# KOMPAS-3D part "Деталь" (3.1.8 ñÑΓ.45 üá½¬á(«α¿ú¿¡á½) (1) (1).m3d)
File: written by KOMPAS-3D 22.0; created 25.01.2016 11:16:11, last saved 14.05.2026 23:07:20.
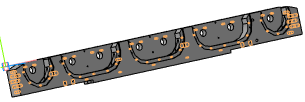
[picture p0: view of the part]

Document properties: Полное имя файла: E:\test_kompas\all_v20\3.1.8 дет.45 Балка(оригинал) (1) (1).m3d

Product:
- Part/product: Деталь
    Масса: 261.985445

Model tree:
1. Эскиз:1
2. Операция выдавливания:1
     Расстояние 1 = 115
3. Эскиз:9  (with: Операция выдавливания:1)
4. Вырезать элемент выдавливания:13
     Расстояние 1 = 115
5. Эскиз:19  (with: Операция выдавливания:1)
6. Вырезать элемент выдавливания:14
     Расстояние 1 = 231
7. Эскиз:20  (with: Операция выдавливания:1)
8. Эскиз:21  (with: Операция выдавливания:1)
9. Вырезать элемент выдавливания:15
     Расстояние 1 = 75
10. Вырезать элемент выдавливания:16
     Расстояние 1 = 10
11. Эскиз:22  (with: Операция выдавливания:1, Вырезать элемент выдавливания:14)
12. Вырезать элемент выдавливания:17
     Расстояние 1 = 30
13. Эскиз:23  (with: Операция выдавливания:1)
14. Вырезать элемент выдавливания:18
     Расстояние 1 = 30
15. Условное изображение резьбы:1  (with: Вырезать элемент выдавливания:17)
     Длина резьбы = 30; Шаг резьбы = 2; Номинальный диаметр резьбы = 20.0651
16. Условное изображение резьбы:2  (with: Вырезать элемент выдавливания:17)
     Длина резьбы = 30; Шаг резьбы = 2; Номинальный диаметр резьбы = 20.0651
17. Условное изображение резьбы:3  (with: Вырезать элемент выдавливания:18)
     Длина резьбы = 30; Шаг резьбы = 2; Номинальный диаметр резьбы = 20.0651
18. Условное изображение резьбы:4  (with: Вырезать элемент выдавливания:18)
     Длина резьбы = 30; Шаг резьбы = 2; Номинальный диаметр резьбы = 20.0651
19. Эскиз:24  (with: Операция выдавливания:1)
20. Вырезать элемент выдавливания:19
     Расстояние 1 = 75
21. Эскиз:25  (with: Операция выдавливания:1)
22. Вырезать элемент выдавливания:20
     Расстояние 1 = 35
23. Условное изображение резьбы:5  (with: Вырезать элемент выдавливания:20)
     Длина резьбы = 35; Шаг резьбы = 1.5; Номинальный диаметр резьбы = 20.0538
24. Условное изображение резьбы:6  (with: Вырезать элемент выдавливания:20)
     Длина резьбы = 35; Шаг резьбы = 1.5; Номинальный диаметр резьбы = 20.0538
25. Условное изображение резьбы:7  (with: Вырезать элемент выдавливания:20)
     Длина резьбы = 35; Шаг резьбы = 1.5; Номинальный диаметр резьбы = 20.0538
26. Условное изображение резьбы:8  (with: Вырезать элемент выдавливания:20)
     Длина резьбы = 35; Шаг резьбы = 1.5; Номинальный диаметр резьбы = 20.0538
27. Условное изображение резьбы:9  (with: Вырезать элемент выдавливания:20)
     Длина резьбы = 35; Шаг резьбы = 1; Номинальный диаметр резьбы = 19.5125
28. Условное изображение резьбы:10  (with: Вырезать элемент выдавливания:20)
     Длина резьбы = 35; Шаг резьбы = 1; Номинальный диаметр резьбы = 19.5125
29. Эскиз:26  (with: Операция выдавливания:1, Вырезать элемент выдавливания:13)
30. Вырезать элемент выдавливания:21
     Расстояние 1 = 35
31. Условное изображение резьбы:11  (with: Вырезать элемент выдавливания:21)
     Длина резьбы = 35; Шаг резьбы = 1.5; Номинальный диаметр резьбы = 20.0538
32. Условное изображение резьбы:12  (with: Вырезать элемент выдавливания:21)
     Длина резьбы = 35; Шаг резьбы = 1.5; Номинальный диаметр резьбы = 20.0538
33. Условное изображение резьбы:13  (with: Вырезать элемент выдавливания:21)
     Длина резьбы = 35; Шаг резьбы = 1.5; Номинальный диаметр резьбы = 20.0538
34. Условное изображение резьбы:14  (with: Вырезать элемент выдавливания:21)
     Длина резьбы = 35; Шаг резьбы = 1.5; Номинальный диаметр резьбы = 20.0538
35. Условное изображение резьбы:15  (with: Вырезать элемент выдавливания:21)
     Длина резьбы = 35; Шаг резьбы = 1.5; Номинальный диаметр резьбы = 20.0538
36. Условное изображение резьбы:16  (with: Вырезать элемент выдавливания:21)
     Длина резьбы = 35; Шаг резьбы = 1.5; Номинальный диаметр резьбы = 20.0538
37. Эскиз:27  (with: Операция выдавливания:1, Вырезать элемент выдавливания:15)
38. Эскиз:28  (with: Операция выдавливания:1)
39. Вырезать элемент выдавливания:22
     Расстояние 1 = 115
40. Эскиз:29  (with: Вырезать элемент выдавливания:16)
41. Вырезать элемент выдавливания:23
     Расстояние 1 = 13
42. Эскиз:30  (with: Вырезать элемент выдавливания:16)
43. Вырезать элемент выдавливания:24
     Расстояние 1 = 13
44. Условное изображение резьбы:17  (with: Вырезать элемент выдавливания:23)
     Длина резьбы = 13; Шаг резьбы = 1; Номинальный диаметр резьбы = 9.51253
45. Условное изображение резьбы:18  (with: Вырезать элемент выдавливания:23)
     Длина резьбы = 13; Шаг резьбы = 1; Номинальный диаметр резьбы = 9.51253
46. Условное изображение резьбы:19  (with: Вырезать элемент выдавливания:23)
     Длина резьбы = 13; Шаг резьбы = 1; Номинальный диаметр резьбы = 9.51253
47. Условное изображение резьбы:20  (with: Вырезать элемент выдавливания:23)
     Длина резьбы = 13; Шаг резьбы = 1; Номинальный диаметр резьбы = 9.51253
48. Условное изображение резьбы:21  (with: Вырезать элемент выдавливания:23)
     Длина резьбы = 13; Шаг резьбы = 1; Номинальный диаметр резьбы = 9.51253
49. Условное изображение резьбы:22  (with: Вырезать элемент выдавливания:24)
     Длина резьбы = 13; Шаг резьбы = 1; Номинальный диаметр резьбы = 9.51253
50. Условное изображение резьбы:23  (with: Вырезать элемент выдавливания:24)
     Длина резьбы = 13; Шаг резьбы = 1; Номинальный диаметр резьбы = 9.51253
51. Условное изображение резьбы:24  (with: Вырезать элемент выдавливания:24)
     Длина резьбы = 13; Шаг резьбы = 1; Номинальный диаметр резьбы = 9.51253
52. Условное изображение резьбы:25  (with: Вырезать элемент выдавливания:24)
     Длина резьбы = 13; Шаг резьбы = 1; Номинальный диаметр резьбы = 9.51253
53. Условное изображение резьбы:26  (with: Вырезать элемент выдавливания:24)
     Длина резьбы = 13; Шаг резьбы = 1; Номинальный диаметр резьбы = 9.51253
54. Эскиз:31  (with: Вырезать элемент выдавливания:16, Вырезать элемент выдавливания:19)
55. Вырезать элемент выдавливания:25
     Расстояние 1 = 13
56. Условное изображение резьбы:27  (with: Вырезать элемент выдавливания:25)
     Длина резьбы = 13; Шаг резьбы = 1; Номинальный диаметр резьбы = 9.51253
57. Условное изображение резьбы:28  (with: Вырезать элемент выдавливания:25)
     Длина резьбы = 13; Шаг резьбы = 1; Номинальный диаметр резьбы = 9.51253
58. Условное изображение резьбы:29  (with: Вырезать элемент выдавливания:25)
     Длина резьбы = 13; Шаг резьбы = 1; Номинальный диаметр резьбы = 9.51253
59. Условное изображение резьбы:30  (with: Вырезать элемент выдавливания:25)
     Длина резьбы = 13; Шаг резьбы = 1; Номинальный диаметр резьбы = 9.51253
60. Условное изображение резьбы:31  (with: Вырезать элемент выдавливания:25)
     Длина резьбы = 13; Шаг резьбы = 1; Номинальный диаметр резьбы = 9.51253
61. Условное изображение резьбы:32  (with: Вырезать элемент выдавливания:25)
     Длина резьбы = 13; Шаг резьбы = 1; Номинальный диаметр резьбы = 9.51253
62. Условное изображение резьбы:33  (with: Вырезать элемент выдавливания:25)
     Длина резьбы = 13; Шаг резьбы = 1; Номинальный диаметр резьбы = 9.51253
63. Эскиз:32  (with: Вырезать элемент выдавливания:16)
64. Вырезать элемент выдавливания:26
     Расстояние 1 = 13
65. Условное изображение резьбы:34  (with: Вырезать элемент выдавливания:26)
     Длина резьбы = 13; Шаг резьбы = 1; Номинальный диаметр резьбы = 9.51253
66. Условное изображение резьбы:35  (with: Вырезать элемент выдавливания:26)
     Длина резьбы = 13; Шаг резьбы = 1; Номинальный диаметр резьбы = 9.51253
67. Условное изображение резьбы:36  (with: Вырезать элемент выдавливания:26)
     Длина резьбы = 13; Шаг резьбы = 1; Номинальный диаметр резьбы = 9.51253
68. Условное изображение резьбы:37  (with: Вырезать элемент выдавливания:26)
     Длина резьбы = 13; Шаг резьбы = 1; Номинальный диаметр резьбы = 9.51253
69. Условное изображение резьбы:38  (with: Вырезать элемент выдавливания:26)
     Длина резьбы = 13; Шаг резьбы = 1; Номинальный диаметр резьбы = 9.51253
70. Условное изображение резьбы:39  (with: Вырезать элемент выдавливания:26)
     Длина резьбы = 13; Шаг резьбы = 1; Номинальный диаметр резьбы = 9.51253
71. Условное изображение резьбы:40  (with: Вырезать элемент выдавливания:26)
     Длина резьбы = 13; Шаг резьбы = 1; Номинальный диаметр резьбы = 9.51253
72. Эскиз:33  (with: Вырезать элемент выдавливания:16)
73. Вырезать элемент выдавливания:27
     Расстояние 1 = 13
74. Условное изображение резьбы:41  (with: Вырезать элемент выдавливания:27)
     Длина резьбы = 13; Шаг резьбы = 1; Номинальный диаметр резьбы = 9.51253
75. Условное изображение резьбы:42  (with: Вырезать элемент выдавливания:27)
     Длина резьбы = 13; Шаг резьбы = 1; Номинальный диаметр резьбы = 9.51253
76. Условное изображение резьбы:43  (with: Вырезать элемент выдавливания:27)
     Длина резьбы = 13; Шаг резьбы = 1; Номинальный диаметр резьбы = 9.51253
77. Условное изображение резьбы:44  (with: Вырезать элемент выдавливания:27)
     Длина резьбы = 13; Шаг резьбы = 1; Номинальный диаметр резьбы = 9.51253
78. Условное изображение резьбы:45  (with: Вырезать элемент выдавливания:27)
     Длина резьбы = 13; Шаг резьбы = 1; Номинальный диаметр резьбы = 9.51253
79. Условное изображение резьбы:46  (with: Вырезать элемент выдавливания:27)
     Длина резьбы = 13; Шаг резьбы = 1; Номинальный диаметр резьбы = 9.51253
80. Условное изображение резьбы:47  (with: Вырезать элемент выдавливания:27)
     Длина резьбы = 13; Шаг резьбы = 1; Номинальный диаметр резьбы = 9.51253
81. Эскиз:34  (with: Операция выдавливания:1)
82. Эскиз:35  (with: Операция выдавливания:1, Вырезать элемент выдавливания:17)
83. Вырезать элемент выдавливания:28
     Расстояние 1 = 94
84. Эскиз:36  (with: Операция выдавливания:1)
85. Вырезать элемент выдавливания:29
     Расстояние 1 = 21
86. Эскиз:37  (with: Вырезать элемент выдавливания:15)
87. Вырезать элемент выдавливания:30
     Расстояние 1 = 40
88. Эскиз:38  (with: Операция выдавливания:1)
89. Вырезать элемент выдавливания:31
     Расстояние 1 = 10
90. Эскиз:39  (with: Операция выдавливания:1)
91. Вырезать элемент выдавливания:32
     Расстояние 1 = 50
92. Условное изображение резьбы:48  (with: Вырезать элемент выдавливания:32)
     Длина резьбы = 50; Шаг резьбы = 1; Номинальный диаметр резьбы = 18.0325
93. Условное изображение резьбы:49  (with: Вырезать элемент выдавливания:32)
     Длина резьбы = 50; Шаг резьбы = 1; Номинальный диаметр резьбы = 18.0325
94. Условное изображение резьбы:50  (with: Вырезать элемент выдавливания:32)
     Длина резьбы = 50; Шаг резьбы = 1; Номинальный диаметр резьбы = 18.0325
95. Условное изображение резьбы:51  (with: Вырезать элемент выдавливания:32)
     Длина резьбы = 50; Шаг резьбы = 1; Номинальный диаметр резьбы = 18.0325
96. Эскиз:40  (with: Операция выдавливания:1, Вырезать элемент выдавливания:13, Вырезать элемент выдавливания:22, Вырезать элемент выдавливания:29)
97. Вырезать элемент выдавливания:33
     Расстояние 1 = 70
98. Условное изображение резьбы:52  (with: Вырезать элемент выдавливания:33)
     Длина резьбы = 70; Шаг резьбы = 1; Номинальный диаметр резьбы = 28.0325
99. Условное изображение резьбы:53  (with: Вырезать элемент выдавливания:33)
     Длина резьбы = 70; Шаг резьбы = 1; Номинальный диаметр резьбы = 28.0325
100. Эскиз:41  (with: Операция выдавливания:1)
101. Вырезать элемент выдавливания:34
     Расстояние 1 = 30
102. Условное изображение резьбы:54  (with: Вырезать элемент выдавливания:34)
     Длина резьбы = 30; Шаг резьбы = 1; Номинальный диаметр резьбы = 8.03253
103. Условное изображение резьбы:55  (with: Вырезать элемент выдавливания:34)
     Длина резьбы = 30; Шаг резьбы = 1; Номинальный диаметр резьбы = 8.03253
104. Условное изображение резьбы:56  (with: Вырезать элемент выдавливания:34)
     Длина резьбы = 30; Шаг резьбы = 1; Номинальный диаметр резьбы = 8.03253
105. Условное изображение резьбы:57  (with: Вырезать элемент выдавливания:34)
     Длина резьбы = 30; Шаг резьбы = 1; Номинальный диаметр резьбы = 8.03253
106. Условное изображение резьбы:58  (with: Вырезать элемент выдавливания:34)
     Длина резьбы = 30; Шаг резьбы = 1; Номинальный диаметр резьбы = 8.03253
107. Вырезать элемент выдавливания:35
     Расстояние 1 = 10
108. Эскиз:42  (with: Операция выдавливания:1, Вырезать элемент выдавливания:33)
109. Вырезать элемент выдавливания:36
     Расстояние 1 = 55
110. Условное изображение резьбы:59  (with: Вырезать элемент выдавливания:36)
     Длина резьбы = 55; Шаг резьбы = 1; Номинальный диаметр резьбы = 16.0325
111. Эскиз:43  (with: Операция выдавливания:1, Вырезать элемент выдавливания:22)
112. Вырезать элемент выдавливания:37
     Расстояние 1 = 30
113. Условное изображение резьбы:60  (with: Вырезать элемент выдавливания:37)
     Длина резьбы = 30; Шаг резьбы = 1; Номинальный диаметр резьбы = 11.0325
114. Условное изображение резьбы:61  (with: Вырезать элемент выдавливания:37)
     Длина резьбы = 30; Шаг резьбы = 1; Номинальный диаметр резьбы = 11.0325
115. Условное изображение резьбы:62  (with: Вырезать элемент выдавливания:37)
     Длина резьбы = 30; Шаг резьбы = 1; Номинальный диаметр резьбы = 11.0325
116. Условное изображение резьбы:63  (with: Вырезать элемент выдавливания:37)
     Длина резьбы = 30; Шаг резьбы = 1; Номинальный диаметр резьбы = 11.0325
117. Условное изображение резьбы:64  (with: Вырезать элемент выдавливания:37)
     Длина резьбы = 30; Шаг резьбы = 1; Номинальный диаметр резьбы = 11.0325
118. Условное изображение резьбы:65  (with: Вырезать элемент выдавливания:37)
     Длина резьбы = 30; Шаг резьбы = 1; Номинальный диаметр резьбы = 11.0325
119. Условное изображение резьбы:66  (with: Вырезать элемент выдавливания:37)
     Длина резьбы = 30; Шаг резьбы = 1; Номинальный диаметр резьбы = 11.0325
120. Условное изображение резьбы:67  (with: Вырезать элемент выдавливания:37)
     Длина резьбы = 30; Шаг резьбы = 1; Номинальный диаметр резьбы = 11.0325
121. Условное изображение резьбы:68  (with: Вырезать элемент выдавливания:37)
     Длина резьбы = 30; Шаг резьбы = 1; Номинальный диаметр резьбы = 11.0325
122. Условное изображение резьбы:69  (with: Вырезать элемент выдавливания:37)
     Длина резьбы = 30; Шаг резьбы = 1; Номинальный диаметр резьбы = 11.0325
123. Условное изображение резьбы:70  (with: Вырезать элемент выдавливания:37)
     Длина резьбы = 30; Шаг резьбы = 1; Номинальный диаметр резьбы = 11.0325
124. Условное изображение резьбы:71  (with: Вырезать элемент выдавливания:37)
     Длина резьбы = 30; Шаг резьбы = 1; Номинальный диаметр резьбы = 11.0325
125. Условное изображение резьбы:72  (with: Вырезать элемент выдавливания:37)
     Длина резьбы = 30; Шаг резьбы = 1; Номинальный диаметр резьбы = 11.0325
126. Условное изображение резьбы:73  (with: Вырезать элемент выдавливания:37)
     Длина резьбы = 30; Шаг резьбы = 1; Номинальный диаметр резьбы = 11.0325
127. Условное изображение резьбы:74  (with: Вырезать элемент выдавливания:37)
     Длина резьбы = 30; Шаг резьбы = 1; Номинальный диаметр резьбы = 11.0325
128. Условное изображение резьбы:75  (with: Вырезать элемент выдавливания:37)  (labels: 4061045924-6285-0-0|0)
     Длина резьбы = 30; Шаг резьбы = 1; Номинальный диаметр резьбы = 11.0325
